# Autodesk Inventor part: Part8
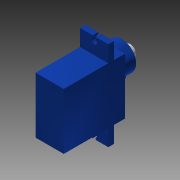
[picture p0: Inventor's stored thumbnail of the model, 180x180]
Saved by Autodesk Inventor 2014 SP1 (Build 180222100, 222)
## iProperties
Created: 2017-05
Part Number: Part8
Material: PPS Plastic
Document SubType Name: Modeling
Designer: L.Đ.P
Density: 1.637 g/cm^3
Appearance: Smooth - White
Author: L.Đ.P
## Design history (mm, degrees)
sketch "Sketch1"
  geometry: L1 (5.075, -10.1)-(-5.075, -10.1); L2 (-5.075, -10.1)-(-5.075, 10.1); L3 (-5.075, 10.1)-(5.075, 10.1); L4 (5.075, 10.1)-(5.075, -10.1); L5 (0, 0)-(0, -6.792); L6 (0, 0)-(-3.426, 0); 2 further points
  constraints: 12 end point, 3 parallel, 2 midpoint, 2 perpendicular, 2 point on line, 1 horizontal
  dimensions: "d0" = 10.15 distance of L2.end L3.end; "d1" = 20.2 distance of L1.end L2.end
extrude "Extrusion1" new body sketch "Sketch1" distance "d2" = 16; taper "d3" = 0 deg
sketch "Sketch2"
  geometry: L1 (5.075, 10.1)-(-5.075, 10.1) reference; L2 (-5.075, 10.1)-(-5.075, -10.1) reference; L3 (5.075, -10.1)-(5.075, 10.1) reference; L4 (5.075, -16)-(-5.075, -16); L5 (-5.075, -16)-(-5.075, 16); L6 (-5.075, 16)-(5.075, 16); L7 (5.075, 16)-(5.075, -16); 3 further points
  constraints: 8 end point, 4 midpoint, 2 parallel, 1 horizontal, 1 perpendicular
  dimensions: "d4" = 32 distance between parallel lines of L4 L6
extrude "Extrusion2" join sketch "Sketch2" distance "d5" = 2; taper "d6" = 0 deg
sketch "Sketch3"
  geometry: L1 (5.075, -16)-(-5.075, -16) reference; L2 (-5.075, -16)-(-5.075, 16) reference; L3 (-5.075, 16)-(5.075, 16) reference; L4 (5.075, 16)-(5.075, -16) reference; L5 (5.075, -16)-(-5.075, -16) reference; L6 (-5.075, -16)-(-5.075, 16) reference; L7 (-5.075, 16)-(5.075, 16) reference; L8 (5.075, 16)-(5.075, -16) reference; L9 (-5.075, 10.1)-(5.075, 10.1) reference; L10 (5.075, 10.1)-(5.075, -10.1) reference; L11 (5.075, -10.1)-(-5.075, -10.1) reference; L12 (-5.075, -10.1)-(-5.075, 10.1) reference; 1 further point
extrude "Extrusion3" join sketch "Sketch3" distance "d7" = 4; taper "d8" = 0 deg
sketch "Sketch4"
  geometry: L1 (-5.075, 10.1)-(-5.075, -10.1) reference; L2 (-5.075, -10.1)-(5.075, -10.1) reference; L3 (5.075, -10.1)-(5.075, 10.1) reference; C1 r 5.075 at (0, -5.025); C2 r 1.5 at (0, 0.675); 1 further point
  constraints: 3 tangent, 2 centre point
  dimensions: "d10" = 3 diameter of C2; "d11" = 5.7 distance of C1.centre C2.centre; "d12" = 5.075 distance from line of L3 C2.centre
extrude "Extrusion4" join sketch "Sketch4" distance "d13" = 4; taper "d14" = 0 deg
sketch "Sketch5"
  geometry: L1 (-5.075, -16)-(5.075, -16) reference; L2 (5.075, -16)-(5.075, -10.1) reference; L3 (0.5, -16)-(-0.5, -16); L4 (-0.5, -16)-(-0.5, -15); L5 (-0.5, -15)-(0.5, -15); L6 (0.5, -15)-(0.5, -16); C1 r 1 at (0, -14.5); 2 further points
  constraints: 8 end point, 2 midpoint, 2 parallel, 1 centre point, 1 horizontal, 1 perpendicular, 1 point on line
  dimensions: "d15" = 2 diameter of C1; "d16" = 1.5 distance from line of L1 C1.centre; "d17" = 1 distance of L4.end L5.end; "d18" = 1 distance of L3.end L4.end; "d19" = 5.075 distance from line of L2 C1.centre
extrude "Extrusion5" cut sketch "Sketch5" distance "d20" = 4; taper "d21" = 0 deg
mirror "Mirror3"
sketch "Sketch11"
  geometry: C1 r 2 at (0, -5.025); A1 r 5.075 centre (0, -5.025) between (-1.276, -0.113) and (1.276, -0.113) reference; 1 further point
  constraints: 1 centre point, 1 coincident
  dimensions: "d49" = 4 diameter of C1
extrude "Extrusion11" join sketch "Sketch11" distance "d50" = 2; taper "d51" = 0 deg
body "Solid1"
node "Projected Loop1"
node "Project Cut Edges1"
node "Project Cut Edges2"
